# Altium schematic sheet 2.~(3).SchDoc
size 420 x 297 mm
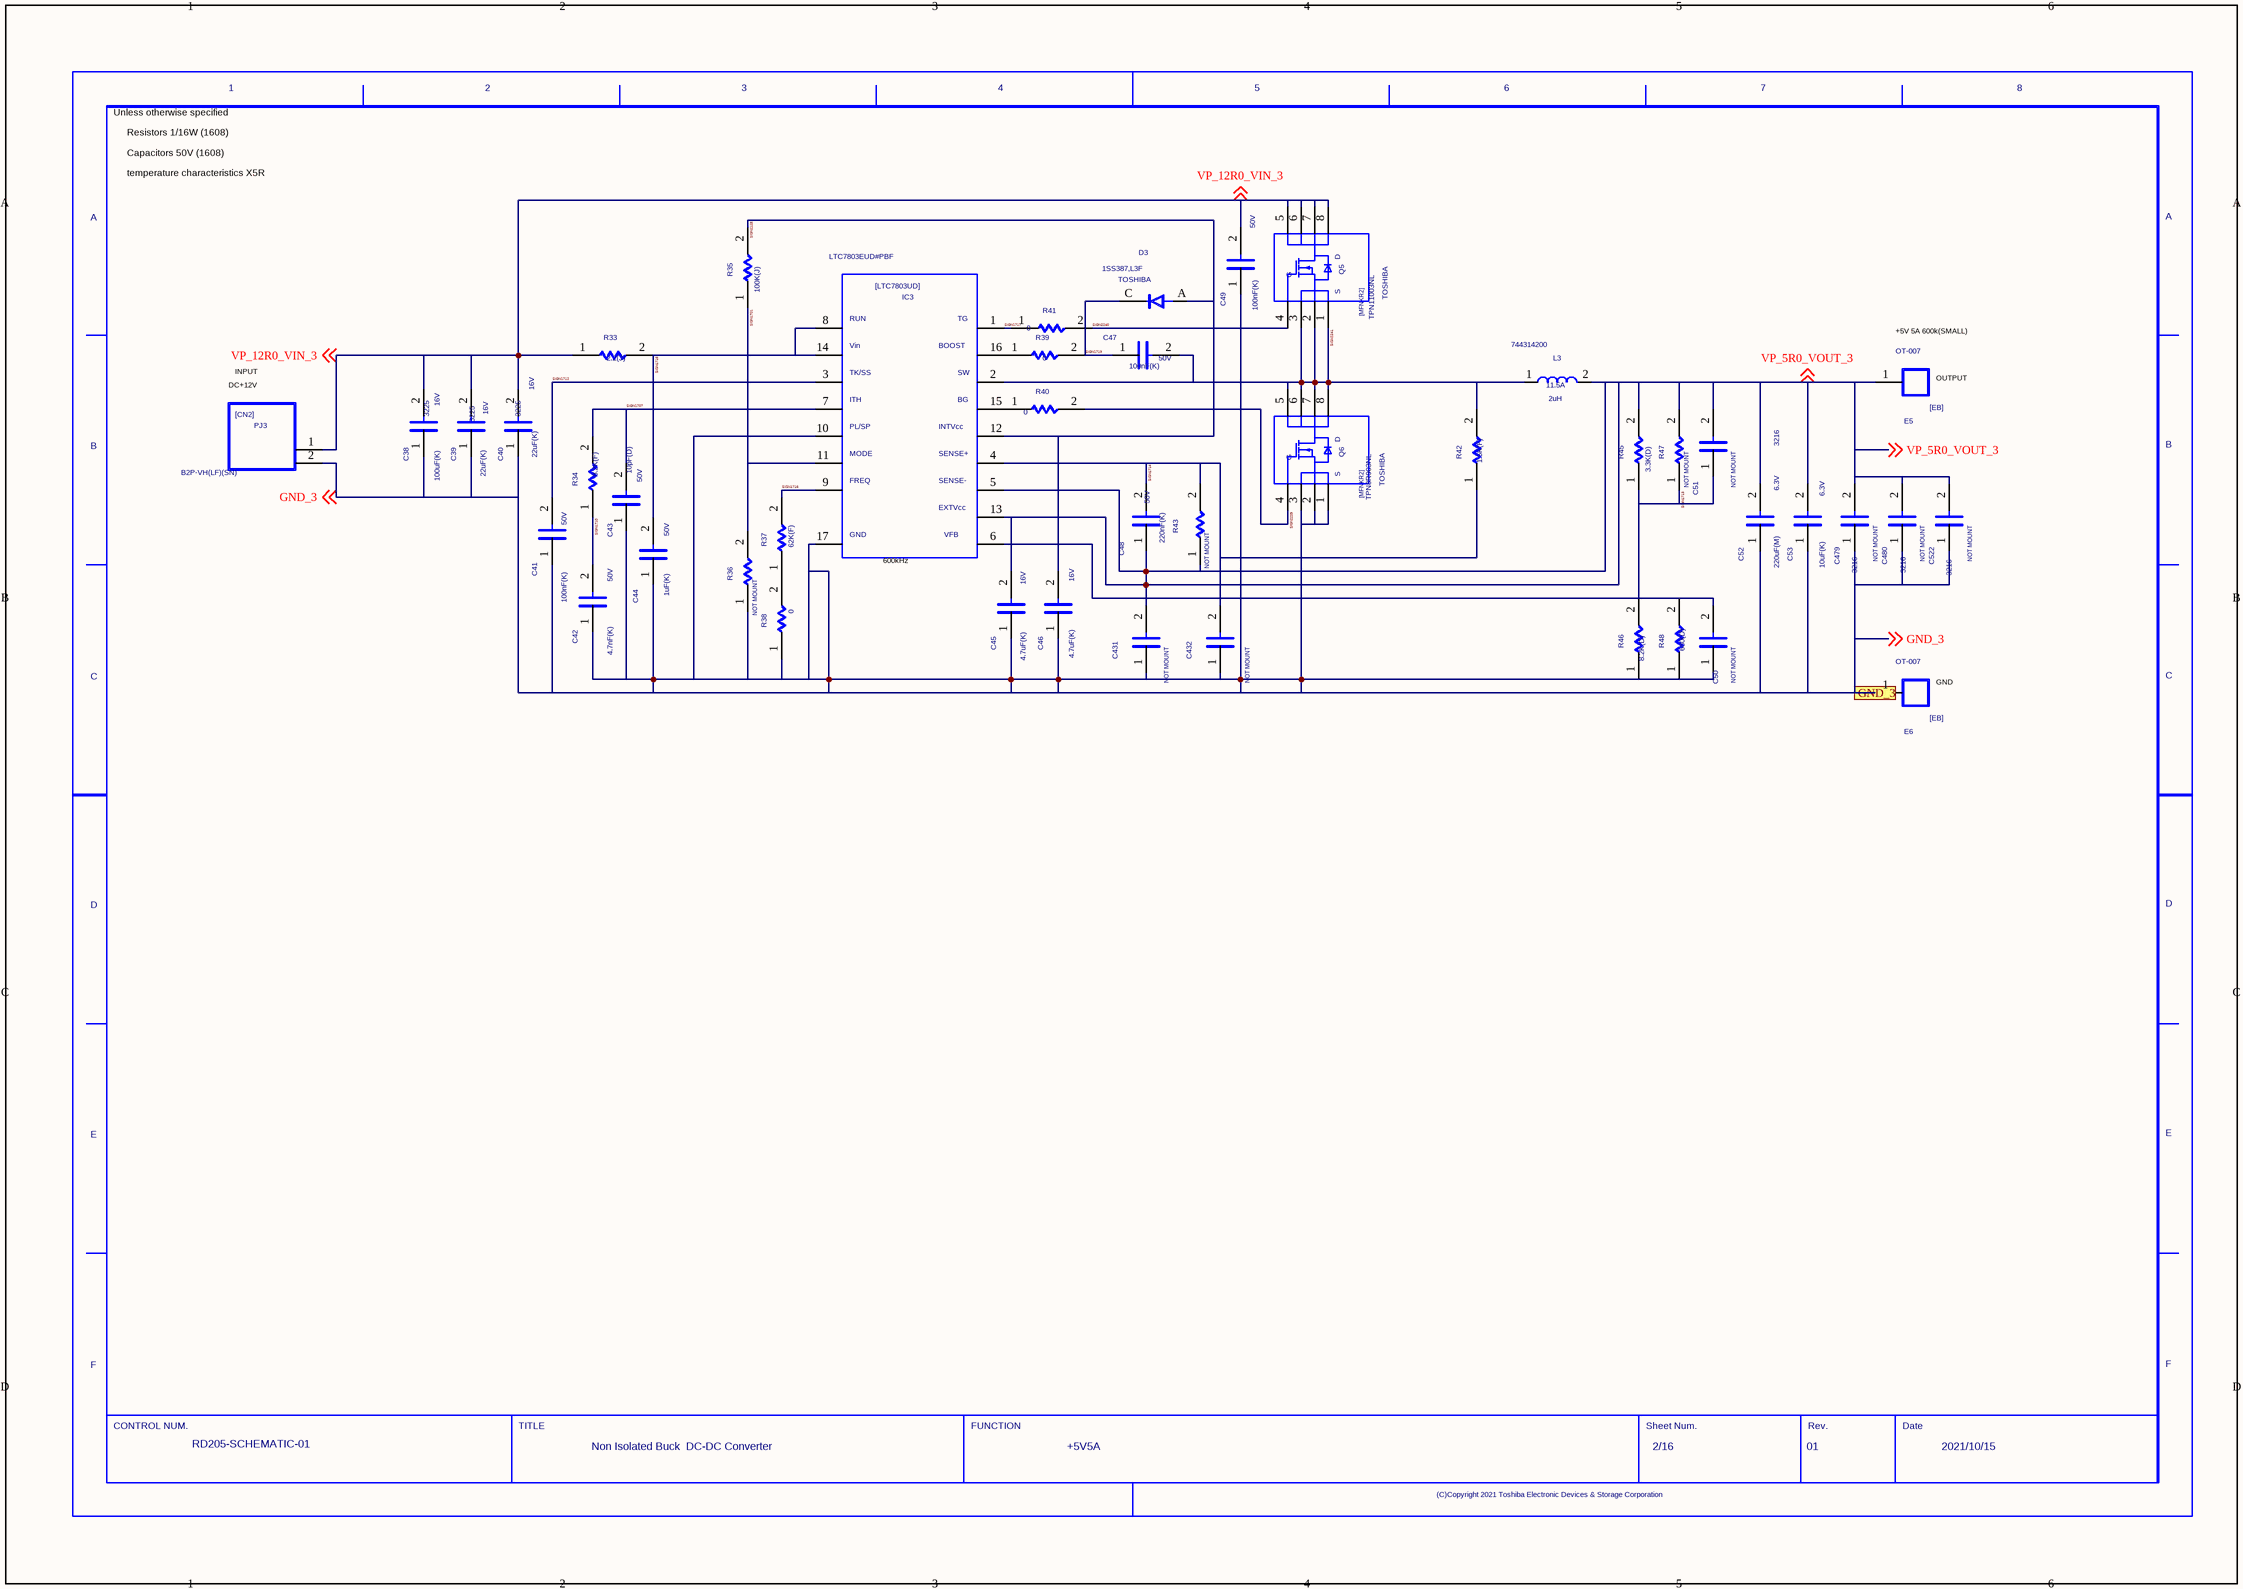
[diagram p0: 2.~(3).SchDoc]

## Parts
C38  SIZECODESMD: 3225  VAL2: 16V  VAL1: 100uF(K)  (hidden comment: C)
C39  SIZECODESMD: 3225  VAL2: 16V  VAL1: 22uF(K)  (hidden comment: C)
C40  SIZECODESMD: 3225  VAL2: 16V  VAL1: 22uF(K)  (hidden comment: C)
C41  VAL2: 50V  VAL1: 100nF(K)  (hidden comment: C)
C42  VAL2: 50V  VAL1: 4.7nF(K)  (hidden comment: C)
C43  VAL2: 50V  VAL1: 10pF(D)  (hidden comment: C)
C44  VAL2: 50V  VAL1: 1uF(K)  (hidden comment: C)
C45  VAL2: 16V  VAL1: 4.7uF(K)  (hidden comment: C)
C46  VAL2: 16V  VAL1: 4.7uF(K)  (hidden comment: C)
C47  VAL2: 50V  VAL1: 100nF(K)  (hidden comment: C)
C48  VAL2: 50V  VAL1: 220nF(K)  (hidden comment: C)
C49  VAL2: 50V  VAL1: 100nF(K)  (hidden comment: C)
C50  NOTMOUNT: NOT MOUNT  (hidden comment: C)
C51  NOTMOUNT: NOT MOUNT  (hidden comment: C)
C52  SIZECODESMD: 3216  VAL2: 6.3V  VAL1: 220uF(M)  (hidden comment: C)
C53  VAL2: 6.3V  VAL1: 10uF(K)  (hidden comment: C)
C431  NOTMOUNT: NOT MOUNT  (hidden comment: C)
C432  NOTMOUNT: NOT MOUNT  (hidden comment: C)
C479  NOTMOUNT: NOT MOUNT  SIZECODESMD: 3216  (hidden comment: C)
C480  NOTMOUNT: NOT MOUNT  SIZECODESMD: 3216  (hidden comment: C)
C522  NOTMOUNT: NOT MOUNT  SIZECODESMD: 3216  (hidden comment: C)
D3  USERCOMPTEXT3: TOSHIBA  VAL3: 1SS387,L3F  (hidden comment: D)
E5  VAL3: OT-007  (hidden comment: EB)
E6  VAL3: OT-007  (hidden comment: EB)
IC3  VAL3: LTC7803EUD#PBF  (hidden comment: LTC7803UD)
L3  VAL3: 744314200  VAL2: 11.5A  VAL1: 2uH  (hidden comment: L)
PJ3  VAL3: B2P-VH(LF)(SN)  (hidden comment: CN2)
Q5  USERCOMPTEXT3: TOSHIBA  VAL3: TPN11003NL  (hidden comment: MFNKR2)
Q6  USERCOMPTEXT3: TOSHIBA  VAL3: TPN8R903NL  (hidden comment: MFNKR2)
R33  VAL1: 2.2(J)  (hidden comment: R)
R34  VAL1: 8.2K(F)  (hidden comment: R)
R35  VAL1: 100K(J)  (hidden comment: R)
R36  NOTMOUNT: NOT MOUNT  (hidden comment: R)
R37  VAL1: 62K(F)  (hidden comment: R)
R38  VAL1: 0  (hidden comment: R)
R39  VAL1: 0  (hidden comment: R)
R40  VAL1: 0  (hidden comment: R)
R41  VAL1: 0  (hidden comment: R)
R42  VAL1: 1.5K(F)  (hidden comment: R)
R43  NOTMOUNT: NOT MOUNT  (hidden comment: R)
R45  VAL1: 3.3K(D)  (hidden comment: R)
R46  VAL1: 8.2K(D)  (hidden comment: R)
R47  NOTMOUNT: NOT MOUNT  (hidden comment: R)
R48  VAL1: 680(D)  (hidden comment: R)
U?  DATE: 2021/10/15  SHEETNUMBER: 2/16  TITLE: Non Isolated Buck / DC-DC Converter  REVISION: 01  DRAWINGNUMBER: RD205-SCHEMATIC-01  FUNCTION: +5V5A  (hidden comment: WAKU_DEF100)

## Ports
GND_3

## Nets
GND_3: C38.1 C39.1 C40.1 C41.1 C42.1 C43.1 C44.1 C45.1 C46.1 C49.1 C50.1 C52.1 C53.1 C431.1 C432.1 C479.1 C480.1 C522.1 E6.1 IC3.10 IC3.17 PJ3.2 Q6.1 Q6.2 Q6.3 R36.1 R38.1 R46.1 R48.1 ; off-sheet GND_3, port GND_3
SIGN1701: IC3.11 R35.1 R36.2
SIGN1707: C43.2 IC3.7 R34.2
SIGN1710: C42.2 R34.1
SIGN1712: C41.2 IC3.3
SIGN1713: C50.2 C51.1 IC3.6 R45.1 R46.2 R47.1 R48.2
SIGN1714: C48.2 C432.2 IC3.4 R42.1 R43.2
SIGN1716: IC3.9 R37.2
SIGN1717: IC3.1 R41.1
SIGN1718: C44.2 IC3.8 IC3.14 R33.2
SIGN1719: C47.1 D3.C R39.2
SIGN2128: C46.2 D3.A IC3.12 R35.2
SIGN2239: Q6.4 R40.2
SIGN2240: Q5.4 R41.2
SIGN2241: C47.2 IC3.2 L3.1 Q5.1 Q5.2 Q5.3 Q6.5 Q6.6 Q6.7 Q6.8 R42.2
VP_5R0_VOUT_3: C45.2 C48.1 C51.2 C52.2 C53.2 C431.2 C479.2 C480.2 C522.2 E5.1 IC3.5 IC3.13 L3.2 R43.1 R45.2 R47.2 ; off-sheet VP_5R0_VOUT_3
VP_12R0_VIN_3: C38.2 C39.2 C40.2 C49.2 PJ3.1 Q5.5 Q5.6 Q5.7 Q5.8 R33.1 ; off-sheet VP_12R0_VIN_3
NetIC3_15: IC3.15 R40.1
NetIC3_16: IC3.16 R39.1
NetR37_1: R37.1 R38.2

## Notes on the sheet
- Unless otherwise specified
- Capacitors 50V (1608)
- Resistors 1/16W (1608)
- temperature characteristics X5R
- DC+12V
- INPUT
- (near E5) +5V 5A 600k(SMALL)
- (near E5) OUTPUT
- (near IC3) 600kHz
- (near E6) GND

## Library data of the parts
C38 = C_Dup1: SQ_PART_MODEL: CON_100n; FNPARTSNAMEG: CHIP CERAMIC CAPACITOR (3225); USEINPARTSLIST: YES; OriginalSymbolOrigin: (2540,7620); MFSOLDERINGPROP: .; TEMPCHARACTERI2: B; MFFORMINGDIVP: KC; OUMECLASSIFICATION: セラミックコンデンサ; MFMOUNTSYMBOLP: 90; CDMASTERCADCELG: DC903A; PCODE: P03276001115; FNCLASSCODEG: P03-03; MAXGCOUNT: 1; RATEDVOLTAGE: 250; COMPONENTNAME: G36030160049; OUMEMAKER: KYC 京セラ; MFPACKAGEMETHOP: S; NOMINALCAPACITA: 100n; OUMEMAKERKATAMEI: CF32W5R104K250AT; CAPACITANCETOLE: K
C39 C40 = C_Dup1: SQ_PART_MODEL: CON_22u; FNPARTSNAMEG: CHIP CERAMIC CAPACITOR (3225); USEINPARTSLIST: YES; OriginalSymbolOrigin: (2540,7620); MFSOLDERINGPROP: .; TEMPCHARACTERI2: B; MFFORMINGDIVP: KC; OUMECLASSIFICATION: セラミックコンデンサ; MFMOUNTSYMBOLP: 80; CDMASTERCADCELG: DC903A; PCODE: P03043035626; FNCLASSCODEG: P03-03; MAXGCOUNT: 1; RATEDVOLTAGE: 6.3; COMPONENTNAME: G36030119054; OUMEMAKER: TYD 太陽誘電; MFPACKAGEMETHOP: S; NOMINALCAPACITA: 22u; OUMEMAKERKATAMEI: JMK325BJ226KM-T; CAPACITANCETOLE: K
C41 C47 C49 = C_Dup1: SQ_PART_MODEL: CON_100n; FNPARTSNAMEG: CHIP CERAMIC CAPACITOR (1608); USEINPARTSLIST: YES; OriginalSymbolOrigin: (2540,7620); MFSOLDERINGPROP: .; TEMPCHARACTERI2: B; MFFORMINGDIVP: KC; OUMECLASSIFICATION: セラミックコンデンサ; SIZECODESMD: 1608; MFMOUNTSYMBOLP: 80; CDMASTERCADCELG: C8100E; PCODE: P03B000000E4; FNCLASSCODEG: P03-03; MAXGCOUNT: 1; RATEDVOLTAGE: 16; COMPONENTNAME: GDM030000598; OUMEMAKER: MRT 村田製作所; MFPACKAGEMETHOP: S; NOMINALCAPACITA: 100n; OUMEMAKERKATAMEI: GRM188B11C104KA01C; CAPACITANCETOLE: K
C42 = C_Dup1: SQ_PART_MODEL: CON_4.7n; FNPARTSNAMEG: CHIP CERAMIC CAPACITOR (1608); USEINPARTSLIST: YES; OriginalSymbolOrigin: (2540,7620); TOLERANCE: K; ASIMVALUE: 4.7N; MFSOLDERINGPROP: .; TEMPCHARACTERI2: B; MFFORMINGDIVP: KC; OUMECLASSIFICATION: セラミックコンデンサ; SIZECODESMD: 1608; MFMOUNTSYMBOLP: 80; CDMASTERCADCELG: C8100E; PCODE: P03039090226; FNCLASSCODEG: P03-03; MAXGCOUNT: 1; RATEDVOLTAGE: 50; COMPONENTNAME: G36030011280; OUMEMAKER: MRT 村田製作所; MFPACKAGEMETHOP: S; OUMEMAKERKATAMEI: GRM39B472K50PT
C43 = C_Dup1: SQ_PART_MODEL: CON_10p; FNPARTSNAMEG: CHIP CERAMIC CAPACITOR (1608); USEINPARTSLIST: YES; OriginalSymbolOrigin: (2540,7620); TOLERANCE: D; ASIMVALUE: 10P; MFSOLDERINGPROP: .; TEMPCHARACTERI2: CH; MFFORMINGDIVP: KC; OUMECLASSIFICATION: セラミックコンデンサ; SIZECODESMD: 1608; MFMOUNTSYMBOLP: 80; CDMASTERCADCELG: C8100E; PCODE: P03039185229; FNCLASSCODEG: P03-03; MAXGCOUNT: 1; RATEDVOLTAGE: 50; COMPONENTNAME: G36030011013; OUMEMAKER: MRT 村田製作所; MFPACKAGEMETHOP: S; OUMEMAKERKATAMEI: GRM39CH100D50PT
C44 = C_Dup1: SQ_PART_MODEL: CON_1u; FNPARTSNAMEG: CHIP CERAMIC CAPACITOR (1608); USEINPARTSLIST: YES; OriginalSymbolOrigin: (2540,7620); MFSOLDERINGPROP: .; TEMPCHARACTERI2: B; MFFORMINGDIVP: KC; OUMECLASSIFICATION: セラミックコンデンサ; SIZECODESMD: 1608; MFMOUNTSYMBOLP: 80; CDMASTERCADCELG: C8100E; PCODE: P03039ACE122; FNCLASSCODEG: P03-03; MAXGCOUNT: 1; RATEDVOLTAGE: 6.3; COMPONENTNAME: G36030104159; OUMEMAKER: KYC 京セラ; MFPACKAGEMETHOP: S; NOMINALCAPACITA: 1u; OUMEMAKERKATAMEI: CM105B105K06ATN; CAPACITANCETOLE: K
C45 = C_Dup1: SQ_PART_MODEL: CON_4.7u; FNPARTSNAMEG: CHIP CERAMIC CAPACITOR (1608); USEINPARTSLIST: YES; OriginalSymbolOrigin: (2540,7620); PCODE: P03B000000MS; MFSOLDERINGPROP: .; TEMPCHARACTERI2: B; MFFORMINGDIVP: KC; OUMECLASSIFICATION: セラミックコンデンサ; SIZECODESMD: 1608; MFMOUNTSYMBOLP: 80; CDMASTERCADCELG: C8100E; FNCLASSCODEG: P03-03; MAXGCOUNT: 1; RATEDVOLTAGE: 4; COMPONENTNAME: GDM030000053; OUMEMAKER: KYC 京セラ; MFPACKAGEMETHOP: S; NOMINALCAPACITA: 4.7u; OUMEMAKERKATAMEI: CM105B475M04AT; CAPACITANCETOLE: M
C46 = C_Dup1: SQ_PART_MODEL: CON_4.7u; FNPARTSNAMEG: CHIP CERAMIC CAPACITOR (1608); USEINPARTSLIST: YES; OriginalSymbolOrigin: (2540,7620); MFSOLDERINGPROP: .; TEMPCHARACTERI2: B; MFFORMINGDIVP: KC; OUMECLASSIFICATION: セラミックコンデンサ; SIZECODESMD: 1608; MFMOUNTSYMBOLP: 80; CDMASTERCADCELG: C8100E; PCODE: P03B000000MS; FNCLASSCODEG: P03-03; MAXGCOUNT: 1; RATEDVOLTAGE: 4; COMPONENTNAME: GDM030000053; OUMEMAKER: KYC 京セラ; MFPACKAGEMETHOP: S; NOMINALCAPACITA: 4.7u; OUMEMAKERKATAMEI: CM105B475M04AT; CAPACITANCETOLE: M
C48 = C_Dup1: SQ_PART_MODEL: CON_220n; FNPARTSNAMEG: CHIP CERAMIC CAPACITOR (1608); PARTCOMMENT: 代表セル<KC0008> がフットプリントに登録されていません。; USEINPARTSLIST: YES; OriginalSymbolOrigin: (2540,7620); MFSOLDERINGPROP: .; TEMPCHARACTERI2: B; MFFORMINGDIVP: KC; OUMECLASSIFICATION: セラミックコンデンサ; SIZECODESMD: 1608; MFMOUNTSYMBOLP: 80; CDMASTERCADCELG: KC0008; PCODE: P03B000001L3; FNCLASSCODEG: P03-03; MAXGCOUNT: 1; RATEDVOLTAGE: 16; COMPONENTNAME: GDM030001129; OUMEMAKER: MRT 村田製作所; MFPACKAGEMETHOP: S; NOMINALCAPACITA: 220n; OUMEMAKERKATAMEI: GRM188B11C224KA01D; CAPACITANCETOLE: K
C50 C51 = C_Dup1: SQ_PART_MODEL: CON_100p; FNPARTSNAMEG: CHIP CERAMIC CAPACITOR (1608); USEINPARTSLIST: YES; OriginalSymbolOrigin: (2540,7620); TOLERANCE: J; ASIMVALUE: 100P; MFSOLDERINGPROP: .; TEMPCHARACTERI2: CH; MFFORMINGDIVP: KC; OUMECLASSIFICATION: セラミックコンデンサ; SIZECODESMD: 1608; MFMOUNTSYMBOLP: 80; CDMASTERCADCELG: C8100E; PCODE: P03039177125; FNCLASSCODEG: P03-03; MAXGCOUNT: 1; RATEDVOLTAGE: 50; COMPONENTNAME: G36030011365; OUMEMAKER: KYC 京セラ; MFPACKAGEMETHOP: S; OUMEMAKERKATAMEI: CM105CH101J50AT; VAL2: 50V; VAL1: 100pF(J)
C52 = C_Dup1: SQ_PART_MODEL: CON_22u; FNPARTSNAMEG: CHIP CERAMIC CAPACITOR (3216); USEINPARTSLIST: YES; OriginalSymbolOrigin: (2540,7620); MFSOLDERINGPROP: .; TEMPCHARACTERI2: B; MFFORMINGDIVP: KC; OUMECLASSIFICATION: セラミックコンデンサ; MFMOUNTSYMBOLP: 80; CDMASTERCADCELG: DC901A; PCODE: P03B0000004V; FNCLASSCODEG: P03-03; MAXGCOUNT: 1; RATEDVOLTAGE: 6.3; COMPONENTNAME: GDM030000020; OUMEMAKER: KYC 京セラ; MFPACKAGEMETHOP: S; NOMINALCAPACITA: 22u; OUMEMAKERKATAMEI: CM316B226M06AT; CAPACITANCETOLE: M
C53 = C_Dup1: SQ_PART_MODEL: CON_1u; FNPARTSNAMEG: CHIP CERAMIC CAPACITOR (1608); PARTCOMMENT: 代表セル<KC0008> がフットプリントに登録されていません。; USEINPARTSLIST: YES; OriginalSymbolOrigin: (2540,7620); MFSOLDERINGPROP: .; TEMPCHARACTERI2: B; MFPACKAGEMETHOP: S; MFFORMINGDIVP: KC; MFMOUNTSYMBOLP: 80; PCODE: P03B000000ZQ; OUMECLASSIFICATION: セラミックコンデンサ; SIZECODESMD: 1608; CDMASTERCADCELG: KC0008; FNCLASSCODEG: P03-03; MAXGCOUNT: 1; RATEDVOLTAGE: 6.3; COMPONENTNAME: GDM030000202; OUMEMAKER: MRT 村田製作所; NOMINALCAPACITA: 1u; OUMEMAKERKATAMEI: GRM185B10J105KE21D; CAPACITANCETOLE: K
C431 C432 = C_Dup1: SQ_PART_MODEL: CON_220n; FNPARTSNAMEG: CHIP CERAMIC CAPACITOR (1608); PARTCOMMENT: 代表セル<KC0008> がフットプリントに登録されていません。; USEINPARTSLIST: YES; OriginalSymbolOrigin: (2540,7620); MFSOLDERINGPROP: .; TEMPCHARACTERI2: B; MFFORMINGDIVP: KC; OUMECLASSIFICATION: セラミックコンデンサ; SIZECODESMD: 1608; MFMOUNTSYMBOLP: 80; CDMASTERCADCELG: KC0008; PCODE: P03B000001L3; FNCLASSCODEG: P03-03; MAXGCOUNT: 1; RATEDVOLTAGE: 16; COMPONENTNAME: GDM030001129; OUMEMAKER: MRT 村田製作所; MFPACKAGEMETHOP: S; NOMINALCAPACITA: 220n; OUMEMAKERKATAMEI: GRM188B11C224KA01D; VAL2: 16V; VAL1: 220nF(K); CAPACITANCETOLE: K
C479 C480 C522 = C_Dup1: SQ_PART_MODEL: CON_22u; FNPARTSNAMEG: CHIP CERAMIC CAPACITOR (3216); USEINPARTSLIST: YES; OriginalSymbolOrigin: (2540,7620); MFSOLDERINGPROP: .; TEMPCHARACTERI2: B; MFFORMINGDIVP: KC; OUMECLASSIFICATION: セラミックコンデンサ; MFMOUNTSYMBOLP: 80; CDMASTERCADCELG: DC901A; PCODE: P03B0000004V; FNCLASSCODEG: P03-03; MAXGCOUNT: 1; RATEDVOLTAGE: 6.3; COMPONENTNAME: GDM030000020; OUMEMAKER: KYC 京セラ; MFPACKAGEMETHOP: S; NOMINALCAPACITA: 22u; OUMEMAKERKATAMEI: CM316B226M06AT; VAL2: 6.3V; VAL1: 22uF(M); CAPACITANCETOLE: M
D3 = D_Dup1: FNPARTSNAMEG: DIODE; USEINPARTSLIST: YES; PARTNAME: GDM420000143; SAVEAREA0: -565,-171,12979,8058; SAVECOUNT: 1; OriginalSymbolOrigin: (2540,5080); FORWARDVOLTAGEM: 0; MAXREVERSEVOLTA: 80; COMPONENTNAME: GDM420000143_package; MFSOLDERINGPROP: .; OUMEMAKER: TSB 東芝（ＹＰＳＳ）; QUADMODEL: dummymodel; MFPACKAGEMETHOP: S; MFFORMINGDIVP: MM; MOUNTINGFORMSMD: SMD; OUMECLASSIFICATION: 小信号ダイオード; OUMEMAKERKATAMEI: 1SS387(TPH3,F); CDMASTERCADCELG: D8101D; PCODE: P42B0000008E; FNCLASSCODEG: P42-01
E5 E6 = EB_Dup1: FNPARTSNAMEG: TERMINAL; USEINPARTSLIST: YES; PARTNAME: 5P9L1232P001; OUMEPARTTYPE: TB; OriginalSymbolOrigin: (2540,12700); COMPONENTNAME: 5P9L1232P001_package; MAXGCOUNT: 1; MFSOLDERINGPROP: .; OUMEMAKER: オサダ; QUADMODEL: dummymodel; MFPACKAGEMETHOP: I; MFFORMINGDIVP: OD; OUMECLASSIFICATION: 端子台、端子板; CDMASTERCADCELG: DE0009; KIND: PBS; PCODE: P29045001117; TERMINALSTYLE: SC; FNCLASSCODEG: P29-01
IC3 = LTC7803UD: USEINPARTSLIST: YES; SAVECOUNT: 29; SAVEAREA0: -53177,0,89020,58420; TIME: 16:14:14; UPDATEUSER: q91866sr; UPDATETIME: 13:15:36; OriginalSymbolOrigin: (5080,55880); MAXGCOUNT: 1; COMPONENTNAME: LTC7803UD_LTC7803UD; OUMEMAKER: ANALOG DEVICES
L3 = L_Dup1: USEINPARTSLIST: YES; PARTNAME: 744311100; OriginalSymbolOrigin: (2540,5080); MAXGCOUNT: 1; COMPONENTNAME: L_L; OUMEMAKER: WURTH
PJ3 = CN2_Dup1: FNPARTSNAMEG: 3.96PITCH NYLON CONNECTOR; USEINPARTSLIST: YES; PARTNAME: G36220114012; OUMEPARTTYPE: CN; OriginalSymbolOrigin: (2540,15240); MAXGCOUNT: 1; RATEDCURRENT: 7; COMPONENTNAME: G36220114012_package; MFSOLDERINGPROP: .; OUMEMAKER: JST 日本圧着端子製造; NUMBEROFCONTACT: 2; QUADMODEL: dummymodel; MFPACKAGEMETHOP: I; MFFORMINGDIVP: CU; CONTACTPITCH: 3.96m; OUMEMAKERKATAMEI: B2P-VH; CDMASTERCADCELG: DPJ514; PCODE: P22346001114; TERMINALSTYLE: PW; FNCLASSCODEG: P22-10
Q5 Q6 = MFNKR2: USEINPARTSLIST: YES; PARTNAME: TPN1R603PL; SAVEAREA0: -9199,-39,32138,22820; TIME: 18:57:44; UPDATEUSER: q91866sr; UPDATETIME: 12:36:02; SAVECOUNT: 10; OriginalSymbolOrigin: (5080,20320); MAXGCOUNT: 1; COMPONENTNAME: MFNKR2_MFNKR2
R33 = R_Dup1: SQ_PART_MODEL: RES_2.2; FNPARTSNAMEG: CHIP RESISTOR (1608); USEINPARTSLIST: YES; OriginalSymbolOrigin: (5080,5080); TOLERANCE: J; ASIMVALUE: 2.2; MAXGCOUNT: 1; COMPONENTNAME: G36010011507; MFSOLDERINGPROP: .; OUMEMAKER: NAE 松下電子部品; MFPACKAGEMETHOP: S; MFFORMINGDIVP: KC; MOUNTINGFORMSMD: SMD; OUMECLASSIFICATION: 表面実装用固定抵抗器; MFMOUNTSYMBOLP: 80; POWERRATING: 63m; OUMEMAKERKATAMEI: ERJ3GEYJ2R2V; NUMBEROFELEMENT: 0; VAL2: 62.5mW; CDMASTERCADCELG: DR802R; PCODE: P01042157622; FNCLASSCODEG: P01-08
R34 = R_Dup1: SQ_PART_MODEL: RES_8.2K; FNPARTSNAMEG: CHIP RESISTOR (1608); USEINPARTSLIST: YES; OriginalSymbolOrigin: (5080,5080); TOLERANCE: F; ASIMVALUE: 8.2K; MAXGCOUNT: 1; COMPONENTNAME: G36010027188; MFSOLDERINGPROP: .; OUMEMAKER: KAM 釜屋電機; MFPACKAGEMETHOP: S; MFFORMINGDIVP: KC; MOUNTINGFORMSMD: SMD; OUMECLASSIFICATION: 表面実装用固定抵抗器; MFMOUNTSYMBOLP: 80; POWERRATING: 63m; OUMEMAKERKATAMEI: RMC1/16-822FTP; NUMBEROFELEMENT: 0; VAL2: 62.5mW; CDMASTERCADCELG: DR802R; PCODE: P01042507328; FNCLASSCODEG: P01-08
R35 = R_Dup1: SQ_PART_MODEL: RES_100K; FNPARTSNAMEG: CHIP RESISTOR (1608); USEINPARTSLIST: YES; OriginalSymbolOrigin: (5080,5080); TOLERANCE: J; ASIMVALUE: 100K; MFSOLDERINGPROP: .; MFPACKAGEMETHOP: S; MFFORMINGDIVP: KC; MOUNTINGFORMSMD: SMD; MFMOUNTSYMBOLP: 80; NUMBEROFELEMENT: 0; PCODE: P01042047220; MAXGCOUNT: 1; COMPONENTNAME: G36010011057; OUMEMAKER: HDK 北陸電気工業; OUMECLASSIFICATION: 表面実装用固定抵抗器; POWERRATING: 63m; OUMEMAKERKATAMEI: CR1/16 104JV; VAL2: 62.5mW; CDMASTERCADCELG: DR802R; FNCLASSCODEG: P01-08
R36 = R_Dup1: SQ_PART_MODEL: RES_10; FNPARTSNAMEG: CHIP RESISTOR (1608); USEINPARTSLIST: YES; OriginalSymbolOrigin: (5080,5080); TOLERANCE: F; ASIMVALUE: 10; MFSOLDERINGPROP: .; MFPACKAGEMETHOP: S; MFFORMINGDIVP: KC; MOUNTINGFORMSMD: SMD; MFMOUNTSYMBOLP: 80; NUMBEROFELEMENT: 0; PCODE: P01042036620; MAXGCOUNT: 1; COMPONENTNAME: G36010104063; OUMEMAKER: NAE 松下電子部品; OUMECLASSIFICATION: 表面実装用固定抵抗器; POWERRATING: 63m; OUMEMAKERKATAMEI: ERJ3GEYF100V; VAL2: 62.5mW; VAL1: 10(F); CDMASTERCADCELG: DR802R; FNCLASSCODEG: P01-08
R37 = R_Dup1: SQ_PART_MODEL: RES_62K; FNPARTSNAMEG: CHIP RESISTOR (1608); USEINPARTSLIST: YES; OriginalSymbolOrigin: (5080,5080); MAXGCOUNT: 1; TOLERANCE: F; COMPONENTNAME: G36010027355; MFSOLDERINGPROP: .; OUMEMAKER: HDK 北陸電気工業; MFPACKAGEMETHOP: S; MFFORMINGDIVP: KC; MOUNTINGFORMSMD: SMD; OUMECLASSIFICATION: 表面実装用固定抵抗器; ASIMVALUE: 62K; MFMOUNTSYMBOLP: 80; POWERRATING: 63m; OUMEMAKERKATAMEI: CR1/16 623FV; NUMBEROFELEMENT: 0; VAL2: 62.5mW; CDMASTERCADCELG: DR802R; PCODE: P01042441226; FNCLASSCODEG: P01-08
R38 = R_Dup1: SQ_PART_MODEL: RES_10; FNPARTSNAMEG: CHIP RESISTOR (1608); USEINPARTSLIST: YES; OriginalSymbolOrigin: (5080,5080); TOLERANCE: F; ASIMVALUE: 10; MAXGCOUNT: 1; COMPONENTNAME: G36010104063; MFSOLDERINGPROP: .; OUMEMAKER: NAE 松下電子部品; MFPACKAGEMETHOP: S; MFFORMINGDIVP: KC; MOUNTINGFORMSMD: SMD; OUMECLASSIFICATION: 表面実装用固定抵抗器; MFMOUNTSYMBOLP: 80; POWERRATING: 63m; OUMEMAKERKATAMEI: ERJ3GEYF100V; VAL2: 62.5mW; CDMASTERCADCELG: DR802R; PCODE: P01042036620; FNCLASSCODEG: P01-08
R39 = R_Dup1: SQ_PART_MODEL: RES_10; FNPARTSNAMEG: CHIP RESISTOR (1608); USEINPARTSLIST: YES; OriginalSymbolOrigin: (5080,5080); TOLERANCE: F; ASIMVALUE: 10; MFSOLDERINGPROP: .; MFPACKAGEMETHOP: S; MFFORMINGDIVP: KC; MOUNTINGFORMSMD: SMD; MFMOUNTSYMBOLP: 80; PCODE: P01042036620; MAXGCOUNT: 1; COMPONENTNAME: G36010104063; OUMEMAKER: NAE 松下電子部品; OUMECLASSIFICATION: 表面実装用固定抵抗器; POWERRATING: 63m; OUMEMAKERKATAMEI: ERJ3GEYF100V; VAL2: 62.5mW; CDMASTERCADCELG: DR802R; FNCLASSCODEG: P01-08
R40 R41 = R_Dup1: SQ_PART_MODEL: RES_10; FNPARTSNAMEG: CHIP RESISTOR (2012); USEINPARTSLIST: YES; OriginalSymbolOrigin: (5080,5080); MAXGCOUNT: 1; TOLERANCE: F; COMPONENTNAME: 5P9L1083P100; MFSOLDERINGPROP: .; OUMEMAKER: 北陸電気工業; MFPACKAGEMETHOP: S; MFFORMINGDIVP: KC; MOUNTINGFORMSMD: SMD; OUMECLASSIFICATION: 表面実装用固定抵抗器; ASIMVALUE: 10; MFMOUNTSYMBOLP: 90; POWERRATING: 100m; OUMEMAKERKATAMEI: CR1/10 100FV Pb(F); VAL2: 125mW; CDMASTERCADCELG: DR910A; PCODE: P01043091222; FNCLASSCODEG: P01-08
R42 = R_Dup1: SQ_PART_MODEL: RES_1.5K; FNPARTSNAMEG: CHIP RESISTOR (1608); USEINPARTSLIST: YES; OriginalSymbolOrigin: (5080,5080); TOLERANCE: F; ASIMVALUE: 1.5K; MAXGCOUNT: 1; COMPONENTNAME: G36010027232; MFSOLDERINGPROP: .; OUMEMAKER: HDK 北陸電気工業; MFPACKAGEMETHOP: S; MFFORMINGDIVP: KC; MOUNTINGFORMSMD: SMD; OUMECLASSIFICATION: 表面実装用固定抵抗器; MFMOUNTSYMBOLP: 80; POWERRATING: 63m; OUMEMAKERKATAMEI: CR1/16 152FV; NUMBEROFELEMENT: 0; VAL2: 62.5mW; CDMASTERCADCELG: DR802R; PCODE: P01042512223; FNCLASSCODEG: P01-08
R43 = R_Dup1: SQ_PART_MODEL: RES_8.2K; FNPARTSNAMEG: CHIP RESISTOR (1608); USEINPARTSLIST: YES; OriginalSymbolOrigin: (5080,5080); TOLERANCE: F; ASIMVALUE: 8.2K; MAXGCOUNT: 1; COMPONENTNAME: G36010027188; MFSOLDERINGPROP: .; OUMEMAKER: KAM 釜屋電機; MFPACKAGEMETHOP: S; MFFORMINGDIVP: KC; MOUNTINGFORMSMD: SMD; OUMECLASSIFICATION: 表面実装用固定抵抗器; MFMOUNTSYMBOLP: 80; POWERRATING: 63m; OUMEMAKERKATAMEI: RMC1/16-822FTP; NUMBEROFELEMENT: 0; VAL2: 62.5mW; VAL1: 8.2K(F); CDMASTERCADCELG: DR802R; PCODE: P01042507328; FNCLASSCODEG: P01-08
R45 = R_Dup1: SQ_PART_MODEL: RES_3.3K; FNPARTSNAMEG: CHIP RESISTOR (1608); USEINPARTSLIST: YES; OriginalSymbolOrigin: (5080,5080); MAXGCOUNT: 1; COMPONENTNAME: G36010014485; MFSOLDERINGPROP: .; OUMEMAKER: SSM 進工業; MFPACKAGEMETHOP: S; MFFORMINGDIVP: KC; MOUNTINGFORMSMD: SMD; OUMECLASSIFICATION: 表面実装用固定抵抗器; RESISTANCETOLER: D; MFMOUNTSYMBOLP: 80; POWERRATING: 63m; OUMEMAKERKATAMEI: RR0816P-332-D; NOMINALRESISTAN: 3.3K; NUMBEROFELEMENT: 0; VAL2: 62.5mW; CDMASTERCADCELG: DR802R; PCODE: P01042249822; FNCLASSCODEG: P01-08
R46 = R_Dup1: ICX_PART_MODEL: RES_8.2K; FNPARTSNAMEG: CHIP RESISTOR (1608); OriginalSymbolOrigin: (5080,5080); FNCLASSCODEG: P01-08; PCODE: P01117051114; CDMASTERCADCELG: DR802R; USEWITHSCHEMA: YES; VAL2: 62.5mW; NUMBEROFELEMENT: 0; NOMINALRESISTAN: 8.2K; OUMEMAKERKATAMEI: RK73G1JTD822D; POWERRATING: 63m; MFMOUNTSYMBOLP: 80; RESISTANCETOLER: D; FUNCTION: G36010129479; OUMECLASSIFICATION: 表面実装用固定抵抗器; MOUNTINGFORMSMD: SMD; MFFORMINGDIVP: KC; MFPACKAGEMETHOP: S; OUMEMAKER: KOA ＫＯＡ; MFSOLDERINGPROP: .; MAXGCOUNT: 1
R47 = R_Dup1: SQ_PART_MODEL: RES_3.3K; FNPARTSNAMEG: CHIP RESISTOR (1608); USEINPARTSLIST: YES; OriginalSymbolOrigin: (5080,5080); TOLERANCE: F; ASIMVALUE: 3.3K; MAXGCOUNT: 1; COMPONENTNAME: G36010027027; MFSOLDERINGPROP: .; OUMEMAKER: ROH ロー・; MFPACKAGEMETHOP: S; MFFORMINGDIVP: KC; MOUNTINGFORMSMD: SMD; OUMECLASSIFICATION: 表面実装用固定抵抗器; MFMOUNTSYMBOLP: 80; POWERRATING: 63m; OUMEMAKERKATAMEI: MCR03EZPFX3301; NUMBEROFELEMENT: 0; VAL2: 62.5mW; VAL1: 3.3K(F); CDMASTERCADCELG: DR802R; PCODE: P01042250729; FNCLASSCODEG: P01-08
R48 = R_Dup1: ICX_PART_MODEL: RES_680; FNPARTSNAMEG: CHIP RESISTOR (1608); OriginalSymbolOrigin: (5080,5080); FNCLASSCODEG: P01-08; PCODE: P01117025115; CDMASTERCADCELG: DR802R; USEWITHSCHEMA: YES; VAL2: 62.5mW; NUMBEROFELEMENT: 0; NOMINALRESISTAN: 680; OUMEMAKERKATAMEI: RK73G1JTD681D; POWERRATING: 63m; MFMOUNTSYMBOLP: 80; RESISTANCETOLER: D; FUNCTION: G36010129219; OUMECLASSIFICATION: 表面実装用固定抵抗器; MOUNTINGFORMSMD: SMD; MFFORMINGDIVP: KC; MFPACKAGEMETHOP: S; OUMEMAKER: KOA ＫＯＡ; MFSOLDERINGPROP: .; MAXGCOUNT: 1
U? = WAKU_DEF100: PLOTTIME: HH:MM; SAVEAREA0: 330961,54,387907,31546; TIME: 19:23:07; UPDATEUSER: t5459927; UPDATETIME: 15:33:38; SAVECOUNT: 6; OriginalSymbolOrigin: (10160,284480); DESIGNED: ***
